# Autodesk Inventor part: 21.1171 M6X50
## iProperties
Created: 2006-02
Part Number: 21.1171 M6X50
Material: Steel, Mild
Description: Cylinder Head Cap Screw
Document SubType Name: Modeling
Standard: DIN 7984
Designer: Andy Moles
Standards Organization: DIN
Language: en-US
Size Designation: M6 x 40
Categories: <MemberInstance><Categories><Category DisplayName="Fasteners" InternalName="e4da775c-781d-43d5-af7c-5136215cf5a6" Mnemonic="FSTN"><Category DisplayName="Bolts"
Density: 7.86 g/cm^3
Mass: 13.1529 g
Surface Area: 12.5505 cm^2
Volume: 1.6734 cm^3
Author: Andy Moles
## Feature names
1. Body [Revolution]
2. Slot [Extrusion]
3. Fillet1
4. Chamfer1
